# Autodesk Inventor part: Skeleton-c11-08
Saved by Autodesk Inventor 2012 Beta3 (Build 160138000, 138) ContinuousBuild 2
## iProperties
Created: 2011-01
Part Number: Skeleton-c11-08
Material: Default
Document SubType Name: Modeling
Designer: Beta-8540w
Density: 1 g/cm^3
_SkeletonDoc: Frame Skeleton File
_Version: 15.0.0
Author: Beta-8540w
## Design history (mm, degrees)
sketch "Reference Skeleton"
  geometry: L1 through (325.691, 1070.446) direction (1, 0); L2 through (404.523, 1164.395) direction (1, 0); 34 other entities
  constraints: 10 horizontal
